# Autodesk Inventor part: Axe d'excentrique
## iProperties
Author: Flavien MARTY
Shininess: 60.0
PropertySet Name: _Private Model Information
Created: 2001-10
Part Number: Axe d'excentrique
Material: Par défaut
Document SubType Name: Modélisation
Designer: Flavien MARTY
Control State: 0
Master: False
Checked Out: False
PropertySet Name: Design Tracking Control
Density: 0.0
Volumn: 0.0
Area: 0.0
PropertySet Name: Model Information
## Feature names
1. Base1
